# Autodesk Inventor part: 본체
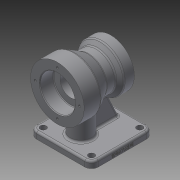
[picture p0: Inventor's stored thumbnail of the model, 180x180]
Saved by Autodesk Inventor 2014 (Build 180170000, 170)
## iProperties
Created: 2019-01
Part Number: 본체
Material: Generic
Document SubType Name: Modeling
Designer: 거성
Density: 1 g/cm^3
Appearance: Default
Author: 거성
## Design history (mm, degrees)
sketch "스케치3"
  geometry: L1 (0, 40)-(0, -40); L2 (26, 40)-(40, 40); L3 (40, 40)-(40, 15); L4 (40, 15)-(28, -5.785); L5 (28, -5.785)-(28, -19.126); L6 (35, -40)-(20, -40); L7 (20, -40)-(20, -23); L8 (20, -23)-(16, -23); L9 (16, -23)-(16, 20); L10 (16, 20)-(26, 20); L11 (26, 20)-(26, 40); L12 (28, -19.126)-(35, -25); L13 (35, -25)-(35, -40); 2 further points
  constraints: 26 end point, 6 parallel, 4 perpendicular, 2 horizontal alignment, 1 coincident, 1 midpoint, 1 vertical
  dimensions: "d0" = 80 distance of L1.start L1.end; "d1" = 80 diameter of L3 L1; "d2" = 52 diameter of L11 L1; "d8" = 25 distance of L2.end L3.end; "d10" = 20 distance of L10.end L2.start; "d14" = 30 deg angle of L4 L5; "d16" = 50 deg angle of L12 L5; "d17" = 70 diameter of L13 L1; "d18" = 40 diameter of L7 L1; "d19" = 32 diameter of L9 L1; "d20" = 15 distance of L12.end L6.start; "d21" = 17 distance of L6.end L7.end; "d22" = 56 diameter of L5 L1
revolve "회전1" sketch "스케치3" stored, may be unused: angle "d23" = 90 deg
node "작업 평면1"
sketch "스케치4"
  geometry: L1 (-40, 40)-(40, 40) reference; L2 (0, 40)-(0, 35); L3 (46, 35)-(-46, 35); L4 (-46, 35)-(-46, -57); L5 (-46, -57)-(46, -57); L6 (46, -57)-(46, 35); L7 (46, 35)-(-46, -57); L8 (-46, 35)-(46, -57); 2 further points
  constraints: 14 end point, 4 midpoint, 2 parallel, 2 perpendicular, 1 horizontal
  dimensions: "d25" = 5 distance of L2.end L2.start; "d26" = 92 distance of L5.end L4.end; "d27" = 92 distance of L4.end L3.end
extrude "돌출1" join sketch "스케치4" distance "d28" = 10; taper "d29" = 0 deg
sketch "스케치5"
  geometry: L1 (-46, -35)-(46, -35) reference; L2 (46, -35)-(46, 57) reference; L3 (-46, 57)-(-46, -35) reference; L4 (-46, -5)-(46, -5); L5 (0, -5)-(0, 57); L6 (-5, 10.199)-(-5, 47); L7 (5, 10.199)-(5, 47); L8 (-5, 47)-(5, 47); L9 (46, 57)-(-46, 57) reference; A1 r 16 centre (0, -5) between (5, 10.199) and (-5, 10.199); 1 further point
  constraints: 10 end point, 2 parallel, 2 perpendicular, 2 point on circle, 2 point on line, 1 centre point, 1 midpoint
  dimensions: "d30" = 30 distance between parallel lines of L1 L4; "d31" = 32 diameter of A1; "d32" = 5 distance between parallel lines of L6 L5; "d33" = 10 distance between parallel lines of L7 L6; "d35" = 10 distance between parallel lines of L8 L9; "d36" = 62 distance of L5.start L5.end
extrude "돌출2" join sketch "스케치5" stored distance "d37" = 10; taper "d38" = 0 deg
node "작업 평면2"
sketch "스케치7"
  geometry: L1 (-70, -57)-(-70, 35) reference; L2 (-28, -19.126)-(-35, -25) reference; L3 (-70, -11)-(-28, -11) reference; L4 (-80, -57)-(-70, -57) reference; L5 (-70, -47)-(-20, -23.685); L6 (-70, -11)-(-70, -47); L7 (-20, -40)-(-20, -23) reference; L8 (-20, -23.685)-(-20, -9.445); L9 (-20, -9.445)-(-70, -9.445); L10 (-70, -11)-(-70, -9.445); 1 further point
  constraints: 10 end point, 3 point on line, 2 collinear, 2 perpendicular
  dimensions: "d46" = 25 deg angle of L5 L4; "d47" = 10 distance from line of L5.start L4; "d58" = 14.23927 distance of L5.end L8.end
extrude "돌출3" join sketch "스케치7" stored distance "d48" = 10; taper "d49" = 0 deg
sketch "스케치10"
  geometry: A1 r 27.5 centre (0, 0) between (0, 27.5) and (27.5, 0); 2 further points
  constraints: 4 point on circle, 1 centre point
  dimensions: "d59" = 55 diameter of A1
hole "구멍2" sketch "스케치10" at (0, -27.5), (27.5, 0), (0, 27.5), (-27.5, 0) diameter "d60" = 3.242; stored, may be unused: countersink angle "d64" = 90 deg, drill point angle "d66" = 118 deg; dims "d61" = 9, "d62" = 4, "d63" = 2, "d65" = 11
sketch "스케치11"
  geometry: C1 r 26 at (0, 0) reference; A1 r 33 centre (0, 0) between (0, 33) and (33, 0); 2 further points
  constraints: 4 point on circle, 1 centre point, 1 coincident
  dimensions: "d67" = 66 diameter of A1
hole "구멍3" sketch "스케치11" at (0, 33), (33, 0), (0, -33), (-33, 0) diameter "d68" = 3.242; stored, may be unused: countersink angle "d72" = 90 deg, drill point angle "d74" = 118 deg; dims "d69" = 9, "d70" = 4, "d71" = 2, "d73" = 11
sketch "스케치13"
  geometry: L1 (0, 0)-(92, 0) reference; L2 (0, 0)-(0, 10) reference; 2 further points
  constraints: 1 other
  dimensions: "d75" = 46 distance from line of point (46, 4) L2; "d76" = 4 distance from line of L1 point (46, 4)
feature "엠보싱1" sketch "스케치13" dims "d0" = 80, "d1" = 80, "d2" = 52, "d8" = 25, "d10" = 20, "d14" = 30 deg, "d16" = 50 deg, "d17" = 70, "d18" = 40, "d19" = 32, "d20" = 15, "d21" = 17, "d22" = 56, "d25" = 5, "d26" = 92, "d27" = 92, "d77" = 0.5, "d78" = 0
fillet "모깎기1" dims "d79" = 10
sketch "스케치14"
  geometry: C1 r 4.5 at (-36, 47); C2 r 4.5 at (36, 47); C3 r 4.5 at (36, -25); C4 r 4.5 at (-36, -25); A1 r 10 centre (36, 47) between (46, 47) and (36, 57) reference; A2 r 10 centre (-36, 47) between (-36, 57) and (-46, 47) reference; A3 r 10 centre (-36, -25) between (-46, -25) and (-36, -35) reference; A4 r 10 centre (36, -25) between (36, -35) and (46, -25) reference; 1 further point
  constraints: 4 centre point, 4 coincident
  dimensions: "d80" = 9 diameter of C1; "d81" = 9 diameter of C2; "d82" = 9 diameter of C3; "d83" = 9 diameter of C4
extrude "돌출4" cut sketch "스케치14" stored distance "d84" = 10; taper "d85" = 0 deg
fillet "모깎기2" dims "d86" = 1
fillet "모깎기3" dims "d87" = 0.6
fillet "모깎기4" dims "d88" = 3
fillet "모깎기5" dims "d89" = 3
fillet "모깎기6" dims "d90" = 3
fillet "모깎기7" dims "d91" = 3
fillet "모깎기8" dims "d92" = 3
chamfer "모따기1" distance "d93" = 1; stored, may be unused: second distance "d94" = 2, angle "d95" = 45 deg
chamfer "모따기2" distance "d96" = 1; stored, may be unused: second distance "d97" = 2, angle "d98" = 45 deg
node "솔리드1"
other parameters: "d43" = 0
